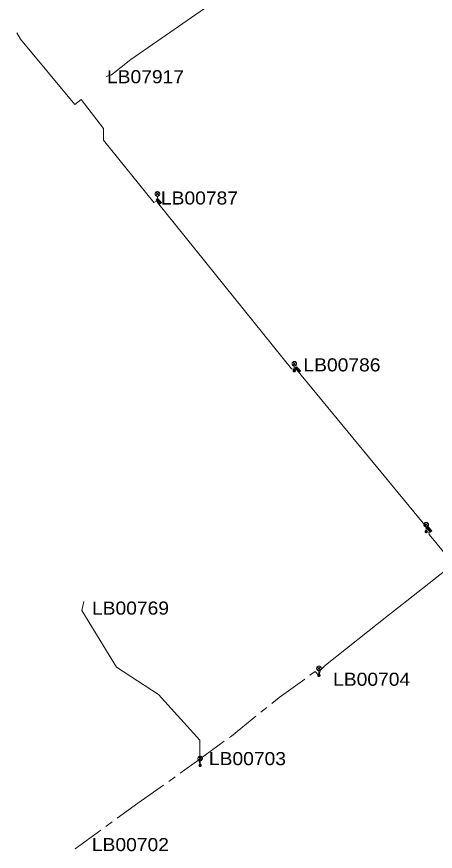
# Model space of a CAD drawing. Extents: x -688049 to -687261, y -973611 to -973038.
# Drawn here: x -688028.2 to -687958.9, y -973302.3 to -973164.2 of the extents above; entities that cross this region are included whole.
import ezdxf

# ---------------------------------------------------------------- set-up
doc = ezdxf.new("R2010")
doc.units = 0
doc.header["$LTSCALE"] = 0.87
doc.linetypes.add('LONG_DASH_SHORT_DASH', pattern=[9.9, 6, -1.2, 1.5, -1.2])
doc.layers.add('1', color=7, linetype='Continuous', lineweight=13)

msp = doc.modelspace()

# ---------------------------------------------------------------- hatches: boundary and pattern name
at = {"layer": '1'}
for points in [[(-688004.899, -973194.244), (-688004.261, -973194.946), (-688004.495, -973195.159), (-688005.133, -973194.457)], [(-688004.865, -973194.469), (-688004.482, -973194.891), (-688004.529, -973194.933), (-688004.912, -973194.512)], [(-687981.867, -973222.107), (-687981.229, -973222.809), (-687981.463, -973223.022), (-687982.101, -973222.32)], [(-687981.833, -973222.332), (-687981.45, -973222.754), (-687981.497, -973222.796), (-687981.88, -973222.375)], [(-687960.142, -973248.561), (-687959.504, -973249.263), (-687959.738, -973249.476), (-687960.376, -973248.774)], [(-687960.108, -973248.786), (-687959.725, -973249.208), (-687959.772, -973249.25), (-687960.155, -973248.829)]]:
    msp.add_hatch(color=256, dxfattribs=at).paths.add_polyline_path(points)

# ---------------------------------------------------------------- linework, layer by layer
for p, q in [((-688005.185, -973193.235), (-688004.655, -973193.765)), ((-688005.185, -973193.765), (-688004.655, -973193.235)), ((-688004.92, -973194.65), (-688004.92, -973193.875)), ((-687982.518, -973221.347), (-687981.988, -973221.877)), ((-687982.518, -973221.877), (-687981.988, -973221.347)), ((-687982.253, -973222.762), (-687982.253, -973221.987)), ((-687981.88, -973222.54), (-687959.867, -973249.256)), ((-687960.678, -973247.981), (-687960.148, -973248.511)), ((-687960.678, -973248.511), (-687960.148, -973247.981)), ((-687960.413, -973249.396), (-687960.413, -973248.621)), ((-687978.445, -973271.785), (-687977.915, -973272.315)), ((-687978.445, -973272.315), (-687977.915, -973271.785)), ((-687978.18, -973273.2), (-687978.18, -973272.425)), ((-687998.115, -973286.685), (-687997.585, -973287.215)), ((-687998.115, -973287.215), (-687997.585, -973286.685)), ((-687998.05, -973287.2), (-687997.85, -973288.1)), ((-687997.85, -973288.1), (-687997.85, -973287.325))]:
    msp.add_line(p, q, dxfattribs=at)
at = {"layer": '1', "linetype": 'LONG_DASH_SHORT_DASH'}
msp.add_line((-687998.05, -973287.2), (-687997.85, -973288.1), dxfattribs=at)
at = {"layer": '1'}
for points in [[(-688013.43, -973174.08), (-688012.55, -973173.78), (-688009.306, -973171.228), (-687992.088, -973159.287), (-687987.773, -973156.273), (-687987.21, -973155.44)], [(-688028.23, -973166.81), (-688027.625, -973167.899), (-688018.596, -973178.713), (-688017.551, -973177.851), (-688013.862, -973182.669), (-688013.862, -973184.614), (-688005.511, -973194.925), (-688004.92, -973194.65)], [(-688004.92, -973194.65), (-688004.92, -973194.945), (-687982.743, -973222.482), (-687981.88, -973222.54)], [(-687959.867, -973249.256), (-687959.977, -973249.491), (-687959.917, -973249.894), (-687955.919, -973254.677), (-687954.965, -973253.869), (-687955.105, -973253.298)], [(-687955.105, -973253.298), (-687954.813, -973253.904), (-687964.366, -973261.482), (-687966.646, -973263.218), (-687977.095, -973271.505), (-687977.93, -973272.313), (-687978.18, -973273.2)], [(-687997.85, -973288.1), (-687997.89, -973287.453), (-687997.89, -973284.714), (-687997.89, -973283.932), (-688004.74, -973276.367), (-688011.691, -973271.837), (-688017.432, -973262.451), (-688017.109, -973260.969)]]:
    msp.add_lwpolyline(points, dxfattribs=at)
for points in [[(-688004.545, -973193.5), (-688004.551, -973193.435), (-688004.568, -973193.372), (-688004.595, -973193.312), (-688004.633, -973193.259), (-688004.679, -973193.213), (-688004.732, -973193.175), (-688004.792, -973193.148), (-688004.855, -973193.131), (-688004.92, -973193.125), (-688004.985, -973193.131), (-688005.048, -973193.148), (-688005.108, -973193.175), (-688005.161, -973193.213), (-688005.207, -973193.259), (-688005.245, -973193.312), (-688005.272, -973193.372), (-688005.289, -973193.435), (-688005.295, -973193.5), (-688005.289, -973193.565), (-688005.272, -973193.628), (-688005.245, -973193.688), (-688005.207, -973193.741), (-688005.161, -973193.787), (-688005.108, -973193.825), (-688005.048, -973193.852), (-688004.985, -973193.869), (-688004.92, -973193.875), (-688004.855, -973193.869), (-688004.792, -973193.852), (-688004.732, -973193.825), (-688004.679, -973193.787), (-688004.633, -973193.741), (-688004.595, -973193.688), (-688004.568, -973193.628), (-688004.551, -973193.565)], [(-688004.899, -973194.244), (-688004.261, -973194.946), (-688004.495, -973195.159), (-688005.133, -973194.457)], [(-688004.899, -973194.244), (-688004.261, -973194.946), (-688004.495, -973195.159), (-688005.133, -973194.457)], [(-688004.865, -973194.469), (-688004.482, -973194.891), (-688004.529, -973194.933), (-688004.912, -973194.512)], [(-687981.878, -973221.612), (-687981.884, -973221.547), (-687981.901, -973221.484), (-687981.928, -973221.424), (-687981.966, -973221.371), (-687982.012, -973221.325), (-687982.066, -973221.287), (-687982.125, -973221.26), (-687982.188, -973221.243), (-687982.253, -973221.237), (-687982.318, -973221.243), (-687982.381, -973221.26), (-687982.44, -973221.287), (-687982.494, -973221.325), (-687982.54, -973221.371), (-687982.578, -973221.424), (-687982.605, -973221.484), (-687982.622, -973221.547), (-687982.628, -973221.612), (-687982.622, -973221.677), (-687982.605, -973221.74), (-687982.578, -973221.8), (-687982.54, -973221.853), (-687982.494, -973221.899), (-687982.44, -973221.937), (-687982.381, -973221.964), (-687982.318, -973221.981), (-687982.253, -973221.987), (-687982.188, -973221.981), (-687982.125, -973221.964), (-687982.066, -973221.937), (-687982.012, -973221.899), (-687981.966, -973221.853), (-687981.928, -973221.8), (-687981.901, -973221.74), (-687981.884, -973221.677)], [(-687981.867, -973222.107), (-687981.229, -973222.809), (-687981.463, -973223.022), (-687982.101, -973222.32)], [(-687981.867, -973222.107), (-687981.229, -973222.809), (-687981.463, -973223.022), (-687982.101, -973222.32)], [(-687981.833, -973222.332), (-687981.45, -973222.754), (-687981.497, -973222.796), (-687981.88, -973222.375)], [(-687982.063, -973222.762), (-687982.066, -973222.729), (-687982.074, -973222.697), (-687982.088, -973222.667), (-687982.107, -973222.64), (-687982.131, -973222.616), (-687982.158, -973222.597), (-687982.188, -973222.583), (-687982.22, -973222.575), (-687982.253, -973222.572), (-687982.286, -973222.575), (-687982.318, -973222.583), (-687982.348, -973222.597), (-687982.375, -973222.616), (-687982.399, -973222.64), (-687982.418, -973222.667), (-687982.432, -973222.697), (-687982.44, -973222.729), (-687982.443, -973222.762), (-687982.44, -973222.795), (-687982.432, -973222.827), (-687982.418, -973222.857), (-687982.399, -973222.884), (-687982.375, -973222.908), (-687982.348, -973222.927), (-687982.318, -973222.941), (-687982.286, -973222.949), (-687982.253, -973222.952), (-687982.22, -973222.949), (-687982.188, -973222.941), (-687982.158, -973222.927), (-687982.131, -973222.908), (-687982.107, -973222.884), (-687982.088, -973222.857), (-687982.074, -973222.827), (-687982.066, -973222.795)], [(-687982.203, -973222.762), (-687982.204, -973222.753), (-687982.206, -973222.745), (-687982.21, -973222.737), (-687982.215, -973222.73), (-687982.221, -973222.724), (-687982.228, -973222.719), (-687982.236, -973222.715), (-687982.244, -973222.713), (-687982.253, -973222.712), (-687982.262, -973222.713), (-687982.27, -973222.715), (-687982.278, -973222.719), (-687982.285, -973222.724), (-687982.291, -973222.73), (-687982.296, -973222.737), (-687982.3, -973222.745), (-687982.302, -973222.753), (-687982.303, -973222.762), (-687982.302, -973222.771), (-687982.3, -973222.779), (-687982.296, -973222.787), (-687982.291, -973222.794), (-687982.285, -973222.8), (-687982.278, -973222.805), (-687982.27, -973222.809), (-687982.262, -973222.811), (-687982.253, -973222.812), (-687982.244, -973222.811), (-687982.236, -973222.809), (-687982.228, -973222.805), (-687982.221, -973222.8), (-687982.215, -973222.794), (-687982.21, -973222.787), (-687982.206, -973222.779), (-687982.204, -973222.771)], [(-687960.038, -973248.246), (-687960.044, -973248.181), (-687960.061, -973248.118), (-687960.088, -973248.059), (-687960.126, -973248.005), (-687960.172, -973247.959), (-687960.226, -973247.921), (-687960.285, -973247.894), (-687960.348, -973247.877), (-687960.413, -973247.871), (-687960.478, -973247.877), (-687960.541, -973247.894), (-687960.6, -973247.921), (-687960.654, -973247.959), (-687960.7, -973248.005), (-687960.738, -973248.059), (-687960.765, -973248.118), (-687960.782, -973248.181), (-687960.788, -973248.246), (-687960.782, -973248.311), (-687960.765, -973248.374), (-687960.738, -973248.434), (-687960.7, -973248.487), (-687960.654, -973248.533), (-687960.6, -973248.571), (-687960.541, -973248.598), (-687960.478, -973248.615), (-687960.413, -973248.621), (-687960.348, -973248.615), (-687960.285, -973248.598), (-687960.226, -973248.571), (-687960.172, -973248.533), (-687960.126, -973248.487), (-687960.088, -973248.434), (-687960.061, -973248.374), (-687960.044, -973248.311)], [(-687960.142, -973248.561), (-687959.504, -973249.263), (-687959.738, -973249.476), (-687960.376, -973248.774)], [(-687960.142, -973248.561), (-687959.504, -973249.263), (-687959.738, -973249.476), (-687960.376, -973248.774)], [(-687960.108, -973248.786), (-687959.725, -973249.208), (-687959.772, -973249.25), (-687960.155, -973248.829)], [(-687960.223, -973249.396), (-687960.226, -973249.363), (-687960.234, -973249.331), (-687960.248, -973249.301), (-687960.267, -973249.274), (-687960.291, -973249.25), (-687960.318, -973249.231), (-687960.348, -973249.217), (-687960.38, -973249.209), (-687960.413, -973249.206), (-687960.446, -973249.209), (-687960.478, -973249.217), (-687960.508, -973249.231), (-687960.535, -973249.25), (-687960.559, -973249.274), (-687960.578, -973249.301), (-687960.592, -973249.331), (-687960.6, -973249.363), (-687960.603, -973249.396), (-687960.6, -973249.429), (-687960.592, -973249.461), (-687960.578, -973249.491), (-687960.559, -973249.518), (-687960.535, -973249.542), (-687960.508, -973249.561), (-687960.478, -973249.575), (-687960.446, -973249.583), (-687960.413, -973249.586), (-687960.38, -973249.583), (-687960.348, -973249.575), (-687960.318, -973249.561), (-687960.291, -973249.542), (-687960.267, -973249.518), (-687960.248, -973249.491), (-687960.234, -973249.461), (-687960.226, -973249.429)], [(-687960.363, -973249.396), (-687960.364, -973249.387), (-687960.366, -973249.379), (-687960.37, -973249.371), (-687960.375, -973249.364), (-687960.381, -973249.358), (-687960.388, -973249.353), (-687960.396, -973249.349), (-687960.404, -973249.347), (-687960.413, -973249.346), (-687960.422, -973249.347), (-687960.43, -973249.349), (-687960.438, -973249.353), (-687960.445, -973249.358), (-687960.451, -973249.364), (-687960.456, -973249.371), (-687960.46, -973249.379), (-687960.462, -973249.387), (-687960.463, -973249.396), (-687960.462, -973249.405), (-687960.46, -973249.413), (-687960.456, -973249.421), (-687960.451, -973249.428), (-687960.445, -973249.434), (-687960.438, -973249.439), (-687960.43, -973249.443), (-687960.422, -973249.445), (-687960.413, -973249.446), (-687960.404, -973249.445), (-687960.396, -973249.443), (-687960.388, -973249.439), (-687960.381, -973249.434), (-687960.375, -973249.428), (-687960.37, -973249.421), (-687960.366, -973249.413), (-687960.364, -973249.405)], [(-687977.805, -973272.05), (-687977.811, -973271.985), (-687977.828, -973271.922), (-687977.855, -973271.862), (-687977.893, -973271.809), (-687977.939, -973271.763), (-687977.992, -973271.725), (-687978.052, -973271.698), (-687978.115, -973271.681), (-687978.18, -973271.675), (-687978.245, -973271.681), (-687978.308, -973271.698), (-687978.368, -973271.725), (-687978.421, -973271.763), (-687978.467, -973271.809), (-687978.505, -973271.862), (-687978.532, -973271.922), (-687978.549, -973271.985), (-687978.555, -973272.05), (-687978.549, -973272.115), (-687978.532, -973272.178), (-687978.505, -973272.237), (-687978.467, -973272.291), (-687978.421, -973272.337), (-687978.368, -973272.375), (-687978.308, -973272.402), (-687978.245, -973272.419), (-687978.18, -973272.425), (-687978.115, -973272.419), (-687978.052, -973272.402), (-687977.992, -973272.375), (-687977.939, -973272.337), (-687977.893, -973272.291), (-687977.855, -973272.237), (-687977.828, -973272.178), (-687977.811, -973272.115)], [(-687977.99, -973273.2), (-687977.993, -973273.167), (-687978.001, -973273.135), (-687978.015, -973273.105), (-687978.034, -973273.078), (-687978.058, -973273.054), (-687978.085, -973273.035), (-687978.115, -973273.021), (-687978.147, -973273.013), (-687978.18, -973273.01), (-687978.213, -973273.013), (-687978.245, -973273.021), (-687978.275, -973273.035), (-687978.302, -973273.054), (-687978.326, -973273.078), (-687978.345, -973273.105), (-687978.359, -973273.135), (-687978.367, -973273.167), (-687978.37, -973273.2), (-687978.367, -973273.233), (-687978.359, -973273.265), (-687978.345, -973273.295), (-687978.326, -973273.322), (-687978.302, -973273.346), (-687978.275, -973273.365), (-687978.245, -973273.379), (-687978.213, -973273.387), (-687978.18, -973273.39), (-687978.147, -973273.387), (-687978.115, -973273.379), (-687978.085, -973273.365), (-687978.058, -973273.346), (-687978.034, -973273.322), (-687978.015, -973273.295), (-687978.001, -973273.265), (-687977.993, -973273.233)], [(-687978.13, -973273.2), (-687978.131, -973273.191), (-687978.133, -973273.183), (-687978.137, -973273.175), (-687978.142, -973273.168), (-687978.148, -973273.162), (-687978.155, -973273.157), (-687978.163, -973273.153), (-687978.171, -973273.151), (-687978.18, -973273.15), (-687978.189, -973273.151), (-687978.197, -973273.153), (-687978.205, -973273.157), (-687978.212, -973273.162), (-687978.218, -973273.168), (-687978.223, -973273.175), (-687978.227, -973273.183), (-687978.229, -973273.191), (-687978.23, -973273.2), (-687978.229, -973273.209), (-687978.227, -973273.217), (-687978.223, -973273.225), (-687978.218, -973273.232), (-687978.212, -973273.238), (-687978.205, -973273.243), (-687978.197, -973273.247), (-687978.189, -973273.249), (-687978.18, -973273.25), (-687978.171, -973273.249), (-687978.163, -973273.247), (-687978.155, -973273.243), (-687978.148, -973273.238), (-687978.142, -973273.232), (-687978.137, -973273.225), (-687978.133, -973273.217), (-687978.131, -973273.209)], [(-687997.475, -973286.95), (-687997.481, -973286.885), (-687997.498, -973286.822), (-687997.525, -973286.763), (-687997.563, -973286.709), (-687997.609, -973286.663), (-687997.662, -973286.625), (-687997.722, -973286.598), (-687997.785, -973286.581), (-687997.85, -973286.575), (-687997.915, -973286.581), (-687997.978, -973286.598), (-687998.038, -973286.625), (-687998.091, -973286.663), (-687998.137, -973286.709), (-687998.175, -973286.763), (-687998.202, -973286.822), (-687998.219, -973286.885), (-687998.225, -973286.95), (-687998.219, -973287.015), (-687998.202, -973287.078), (-687998.175, -973287.138), (-687998.137, -973287.191), (-687998.091, -973287.237), (-687998.038, -973287.275), (-687997.978, -973287.302), (-687997.915, -973287.319), (-687997.85, -973287.325), (-687997.785, -973287.319), (-687997.722, -973287.302), (-687997.662, -973287.275), (-687997.609, -973287.237), (-687997.563, -973287.191), (-687997.525, -973287.138), (-687997.498, -973287.078), (-687997.481, -973287.015)], [(-687997.66, -973288.1), (-687997.663, -973288.067), (-687997.671, -973288.035), (-687997.685, -973288.005), (-687997.704, -973287.978), (-687997.728, -973287.954), (-687997.755, -973287.935), (-687997.785, -973287.921), (-687997.817, -973287.913), (-687997.85, -973287.91), (-687997.883, -973287.913), (-687997.915, -973287.921), (-687997.945, -973287.935), (-687997.972, -973287.954), (-687997.996, -973287.978), (-687998.015, -973288.005), (-687998.029, -973288.035), (-687998.037, -973288.067), (-687998.04, -973288.1), (-687998.037, -973288.133), (-687998.029, -973288.165), (-687998.015, -973288.195), (-687997.996, -973288.222), (-687997.972, -973288.246), (-687997.945, -973288.265), (-687997.915, -973288.279), (-687997.883, -973288.287), (-687997.85, -973288.29), (-687997.817, -973288.287), (-687997.785, -973288.279), (-687997.755, -973288.265), (-687997.728, -973288.246), (-687997.704, -973288.222), (-687997.685, -973288.195), (-687997.671, -973288.165), (-687997.663, -973288.133)], [(-687997.8, -973288.1), (-687997.801, -973288.091), (-687997.803, -973288.083), (-687997.807, -973288.075), (-687997.812, -973288.068), (-687997.818, -973288.062), (-687997.825, -973288.057), (-687997.833, -973288.053), (-687997.841, -973288.051), (-687997.85, -973288.05), (-687997.859, -973288.051), (-687997.867, -973288.053), (-687997.875, -973288.057), (-687997.882, -973288.062), (-687997.888, -973288.068), (-687997.893, -973288.075), (-687997.897, -973288.083), (-687997.899, -973288.091), (-687997.9, -973288.1), (-687997.899, -973288.109), (-687997.897, -973288.117), (-687997.893, -973288.125), (-687997.888, -973288.132), (-687997.882, -973288.138), (-687997.875, -973288.143), (-687997.867, -973288.147), (-687997.859, -973288.149), (-687997.85, -973288.15), (-687997.841, -973288.149), (-687997.833, -973288.147), (-687997.825, -973288.143), (-687997.818, -973288.138), (-687997.812, -973288.132), (-687997.807, -973288.125), (-687997.803, -973288.117), (-687997.801, -973288.109)]]:
    msp.add_lwpolyline(points, close=True, dxfattribs=at)
at = {"layer": '1', "linetype": 'LONG_DASH_SHORT_DASH'}
for points in [[(-687998.05, -973287.2), (-687992.68, -973283.25), (-687984.76, -973276.85), (-687978.78, -973272.55), (-687978.18, -973273.2)], [(-688018.54, -973301.92), (-688008.17, -973294.37), (-687998.05, -973287.2)]]:
    msp.add_lwpolyline(points, dxfattribs=at)

# ---------------------------------------------------------------- texts
at = {"layer": '1', "width": 1.1}
for s, p in [('LB07917', (-688013.28, -973175.182)), ('LB00787', (-688004.345, -973195.257)), ('LB00786', (-687980.743, -973222.881)), ('LB00769', (-688015.766, -973263.146)), ('LB00704', (-687975.828, -973274.926)), ('LB00703', (-687996.395, -973288.062)), ('LB00702', (-688015.779, -973302.294))]:
    msp.add_text(s, height=2.167, dxfattribs=at).set_placement(p)

doc.saveas('drawing.dxf')
